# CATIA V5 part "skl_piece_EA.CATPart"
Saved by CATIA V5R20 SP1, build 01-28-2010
Part number: skl_piece_EA
Publications: "Point.2", "Droite.1", "Droite.2", "Droite.3", "Plan.1", "A", "E"
Bounding box of the stored display mesh (mm): x -13.059 to 23.455, y -20 to 30, z -3.859 to 63.705
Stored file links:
  C:\Users\Matthieu\Desktop\IAO_2012_mcamard_Catia\skl_piece_EA.CATPart
  C:\Users\Matthieu\Desktop\IAO_Artobolevsky\skl_Artoboloevsky_786.CATProduct
  C:\Users\Matthieu\Desktop\IAO_2012_mcamard_Catia\skl_bielle_EF.CATPart
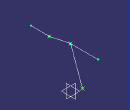
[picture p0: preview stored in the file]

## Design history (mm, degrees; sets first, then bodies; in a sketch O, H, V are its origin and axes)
Set1
  Point1: type OnPlane, Support Plane1, H 13.059, V -3.859, Direction (-1, 0, 0)
  Line1: type PtPt, FirstPoint Point3, SecondPoint Point2
  Line2: type Normal, RefPoint Point3, RefSkin Plane1, Start 0, End 20
  Line3: type PtPt, FirstPoint Point1, SecondPoint Point2
  Line4: type Normal, RefPoint Point2, RefSkin Plane1, Start 0, End 30
Set2
  Plane1: linked copy from another document
  Point2 "A": linked copy from another document
  Point3 "E": linked copy from another document
Body1 (main body)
